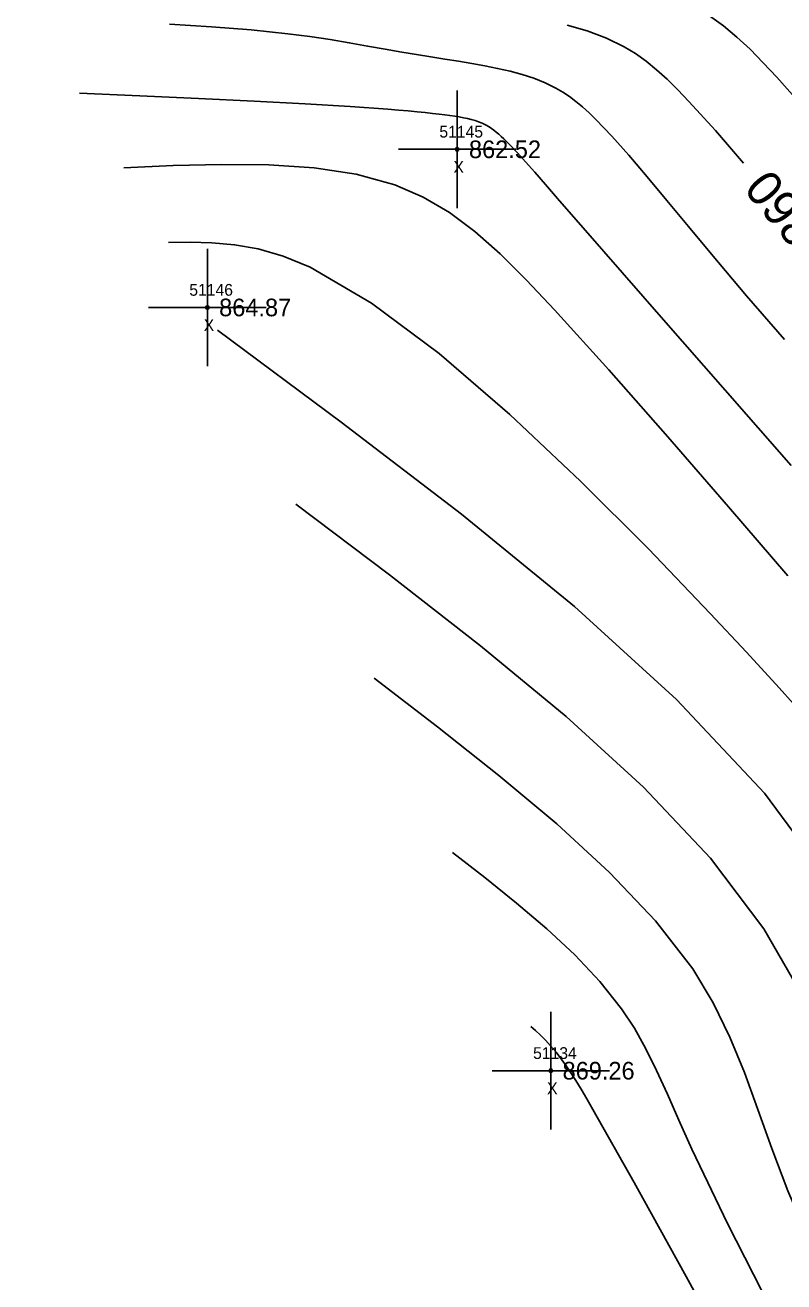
# Model space of a CAD drawing. Extents: x 1378535 to 1380697, y 997729 to 1000024.
# Drawn here: x 1380345.6 to 1380410.2, y 998055.6 to 998162.6 of the extents above; entities that cross this region are included whole.
import ezdxf

# ---------------------------------------------------------------- set-up
doc = ezdxf.new("R2010")
doc.units = 0
for name, color, linetype in [('RD_DTM_BkLn1', 7, 'Continuous'), ('RD_DTM_Major1', 7, 'Continuous'), ('RD_DTM_Major1_Lbl', 7, 'Continuous'), ('RD_DTM_Minor1', 7, 'Continuous'), ('RD_EX_Misc', 7, 'Continuous'), ('RD_EX_Misc_txCode', 7, 'Continuous'), ('RD_EX_Road', 7, 'Continuous'), ('RD_EX_TX_Misc_ELEV', 7, 'Continuous'), ('RD_SMD_Locator', 7, 'Continuous')]:
    doc.layers.add(name, color=color, linetype=linetype)

msp = doc.modelspace()

# ---------------------------------------------------------------- linework, layer by layer
at = {"layer": 'RD_DTM_BkLn1'}
msp.add_spline([(1380561.34, 997899.22), (1380543.7, 997960.78), (1380525.01, 998016.6), (1380501.32, 998075.31), (1380476.75, 998129.12), (1380448.82, 998181.2), (1380418.35, 998233.12), (1380383.22, 998285.15), (1380349.47, 998331.42), (1380310.82, 998378.03), (1380271.62, 998420.47), (1380231.53, 998459.85)], degree=3, dxfattribs=at)
at = {"layer": 'RD_DTM_Major1'}
for points in [[(1380406.76, 998150.82), (1380404.38, 998153.58), (1380402.12, 998156.07), (1380401.17, 998157.06), (1380400.26, 998157.95), (1380399.36, 998158.76), (1380398.47, 998159.48), (1380397.56, 998160.13), (1380396.61, 998160.71), (1380395.09, 998161.45), (1380393.46, 998162.06), (1380391.75, 998162.56)], [(1380424.52, 998063.97), (1380423.75, 998066.64), (1380422.1, 998072.16), (1380420.15, 998077.79), (1380417.69, 998083.46), (1380414.52, 998089.15), (1380408.56, 998097.19), (1380401.07, 998105.17), (1380392.37, 998113.08), (1380382.75, 998120.94), (1380372.52, 998128.78), (1380361.99, 998136.6)]]:
    msp.add_lwpolyline(points, dxfattribs=at)
at = {"layer": 'RD_DTM_Minor1'}
for points in [[(1380410.25, 998135.8), (1380407.03, 998139.53), (1380404.03, 998143.07), (1380402.07, 998145.43), (1380400.25, 998147.63), (1380398.56, 998149.66), (1380397, 998151.49), (1380395.55, 998153.12), (1380394.2, 998154.52), (1380393.62, 998155.08), (1380393.06, 998155.59), (1380392.5, 998156.05), (1380391.94, 998156.48), (1380391.37, 998156.86), (1380390.79, 998157.2), (1380389.87, 998157.65), (1380388.92, 998158.04), (1380387.92, 998158.36), (1380386.89, 998158.63), (1380385.83, 998158.87), (1380384.74, 998159.09), (1380383.63, 998159.29), (1380382.49, 998159.48), (1380381.33, 998159.66), (1380380.14, 998159.85), (1380378.93, 998160.05), (1380377.68, 998160.25), (1380376.25, 998160.51), (1380374.76, 998160.78), (1380373.2, 998161.05), (1380371.57, 998161.32), (1380369.83, 998161.59), (1380367.98, 998161.83), (1380364.86, 998162.15), (1380361.48, 998162.42), (1380357.9, 998162.64)], [(1380411.6, 998155.88), (1380409.59, 998158.13), (1380408.44, 998159.36), (1380407.32, 998160.5), (1380406.21, 998161.54), (1380405.07, 998162.49), (1380403.88, 998163.35)], [(1380410.81, 998125.09), (1380405.2, 998131.48), (1380399.76, 998137.7), (1380394.88, 998143.28), (1380390.94, 998147.81), (1380389.91, 998149), (1380389.01, 998150.03), (1380388.21, 998150.93), (1380387.52, 998151.7), (1380386.91, 998152.34), (1380386.37, 998152.88), (1380386.14, 998153.09), (1380385.92, 998153.29), (1380385.71, 998153.46), (1380385.51, 998153.62), (1380385.31, 998153.77), (1380385.11, 998153.9), (1380384.81, 998154.07), (1380384.52, 998154.21), (1380384.21, 998154.34), (1380383.91, 998154.44), (1380383.59, 998154.53), (1380383.27, 998154.61), (1380382.92, 998154.68), (1380382.56, 998154.75), (1380382.18, 998154.81), (1380381.77, 998154.87), (1380381.33, 998154.92), (1380380.86, 998154.98), (1380380.29, 998155.04), (1380379.66, 998155.11), (1380378.97, 998155.18), (1380378.22, 998155.25), (1380377.39, 998155.33), (1380376.48, 998155.4), (1380373.29, 998155.62), (1380369.45, 998155.85), (1380365.1, 998156.08), (1380360.36, 998156.31), (1380355.36, 998156.55), (1380350.23, 998156.78)], [(1380410.53, 998115.7), (1380405.49, 998121.57), (1380400.32, 998127.53), (1380395.3, 998133.23), (1380390.68, 998138.32), (1380388.29, 998140.86), (1380386.05, 998143.08), (1380383.89, 998145), (1380381.72, 998146.61), (1380379.48, 998147.93), (1380377.08, 998148.97), (1380373.79, 998149.88), (1380370.2, 998150.42), (1380366.36, 998150.68), (1380362.35, 998150.71), (1380358.22, 998150.6), (1380354.02, 998150.42)], [(1380412.23, 998103.44), (1380409.79, 998106.17), (1380407.03, 998109.19), (1380403.94, 998112.49), (1380398.67, 998117.99), (1380392.9, 998123.76), (1380386.87, 998129.43), (1380380.85, 998134.6), (1380375.09, 998138.9), (1380369.86, 998141.96), (1380367.57, 998142.9), (1380365.44, 998143.51), (1380363.43, 998143.87), (1380361.51, 998144.04), (1380359.65, 998144.08), (1380357.82, 998144.06)], [(1380420.76, 998054.63), (1380418.72, 998059.75), (1380417.2, 998064.22), (1380415.82, 998068.61), (1380414.43, 998072.93), (1380412.85, 998077.2), (1380410.93, 998081.44), (1380408.5, 998085.66), (1380403.95, 998091.68), (1380398.26, 998097.7), (1380391.66, 998103.72), (1380384.37, 998109.74), (1380376.63, 998115.77), (1380368.65, 998121.79)], [(1380416.04, 998051.32), (1380413.06, 998057.52), (1380410.55, 998063.37), (1380409.19, 998066.95), (1380407.99, 998070.28), (1380406.84, 998073.43), (1380405.61, 998076.44), (1380404.18, 998079.36), (1380402.44, 998082.24), (1380399.26, 998086.34), (1380395.36, 998090.45), (1380390.86, 998094.58), (1380385.92, 998098.71), (1380380.7, 998102.84), (1380375.32, 998106.98)], [(1380409.08, 998053.34), (1380405.41, 998060.57), (1380402.37, 998066.91), (1380401.27, 998069.37), (1380400.28, 998071.58), (1380399.36, 998073.6), (1380398.45, 998075.45), (1380397.48, 998077.19), (1380396.39, 998078.85), (1380394.54, 998081.16), (1380392.4, 998083.43), (1380390.01, 998085.65), (1380387.44, 998087.84), (1380384.74, 998090.01), (1380381.99, 998092.16)], [(1380406.77, 998047.13), (1380401.89, 998056.06), (1380397.47, 998064.08), (1380393.95, 998070.29), (1380393.42, 998071.2), (1380392.93, 998072.01), (1380392.48, 998072.75), (1380392.06, 998073.4), (1380391.67, 998073.99), (1380391.3, 998074.51), (1380390.81, 998075.16), (1380390.34, 998075.71), (1380389.9, 998076.19), (1380389.48, 998076.61), (1380389.06, 998076.99), (1380388.66, 998077.35)]]:
    msp.add_lwpolyline(points, dxfattribs=at)
at = {"layer": 'RD_EX_Misc'}
for p, q in [((1380382.39, 998146.99), (1380382.39, 998156.99)), ((1380377.39, 998151.99), (1380387.39, 998151.99)), ((1380361.12, 998133.53), (1380361.12, 998143.53)), ((1380356.12, 998138.53), (1380366.12, 998138.53)), ((1380390.36, 998068.58), (1380390.36, 998078.58)), ((1380385.36, 998073.58), (1380395.36, 998073.58))]:
    msp.add_line(p, q, dxfattribs=at)
at = {"layer": 'RD_EX_Road'}
for points in [[(1380571.28, 997900.85), (1380553.84, 997963.23), (1380535.07, 998018.79), (1380510.81, 998079.18), (1380486.36, 998133.16), (1380458.39, 998185.94), (1380428.11, 998238.22), (1380392.69, 998291.14), (1380357.52, 998337.62), (1380319.37, 998385.16), (1380279.26, 998428.68), (1380239.6, 998468.13), (1380183.37, 998518.83)], [(1380551.89, 997897.33), (1380534.24, 997958.2), (1380514.83, 998013.47), (1380491.08, 998070.75), (1380467.52, 998124.4), (1380439.88, 998176.53), (1380409.17, 998228.12), (1380375.89, 998278.45), (1380340.75, 998326.22), (1380303.33, 998371.14), (1380263.98, 998413.97), (1380224.66, 998452.64), (1380168.71, 998504.79)]]:
    msp.add_spline(points, degree=3, dxfattribs=at)
at = {"layer": 'RD_SMD_Locator'}
for centre in [(1380382.39, 998151.99), (1380361.12, 998138.53), (1380390.36, 998073.58)]:
    msp.add_circle(centre, 0.15, dxfattribs=at)

# ---------------------------------------------------------------- texts
at = {"layer": 'RD_DTM_Major1_Lbl'}
msp.add_text('860', height=3, rotation=129.7061, dxfattribs=at).set_placement((1380413.28, 998145.35))
at = {"layer": 'RD_EX_Misc_txCode'}
for s, p in [('51145', (1380380.87, 998152.99)), ('X', (1380382.07, 998149.99)), ('51146', (1380359.58, 998139.53)), ('X', (1380360.81, 998136.53)), ('51134', (1380388.85, 998074.58)), ('X', (1380390.04, 998071.58))]:
    msp.add_text(s, height=1, dxfattribs=at).set_placement(p)
at = {"layer": 'RD_EX_TX_Misc_ELEV'}
for s, p in [('862.52', (1380383.39, 998151.24)), ('864.87', (1380362.12, 998137.78)), ('869.26', (1380391.36, 998072.83))]:
    msp.add_text(s, height=1.5, dxfattribs=at).set_placement(p)

doc.saveas('drawing.dxf')
